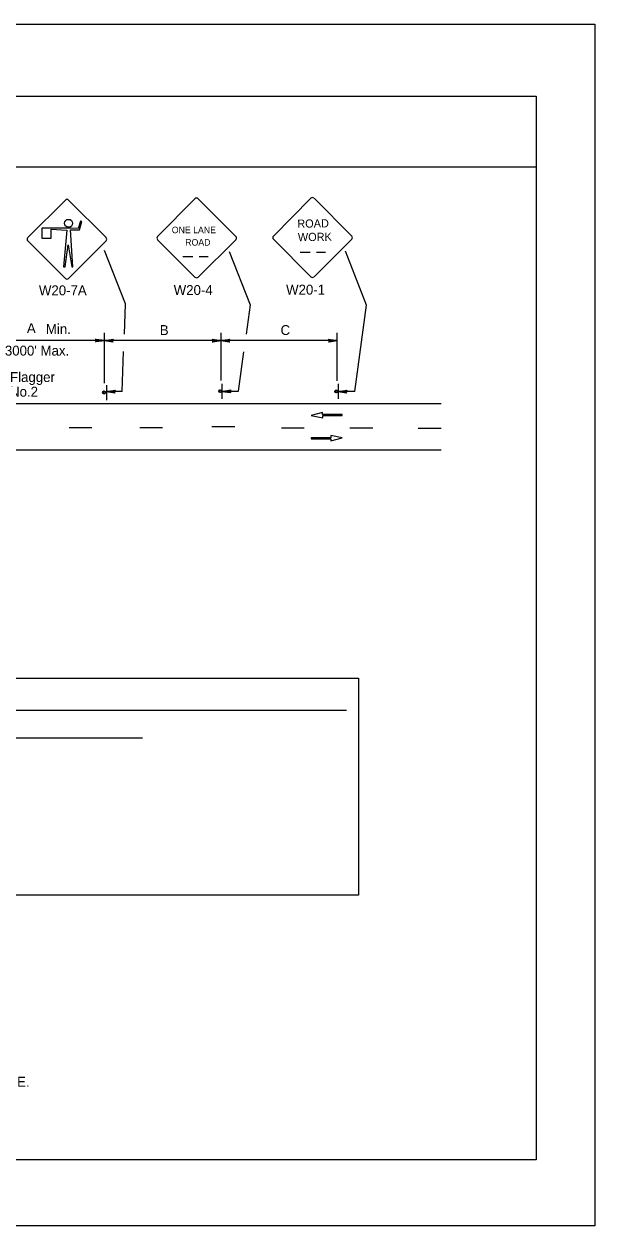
# Model space of a CAD drawing. Extents: x -14145 to -13521, y 30244 to 30661.
# Drawn here: x -13735.29 to -13723.17, y 30451.81 to 30477.31 of the extents above; entities that cross this region are included whole.
import ezdxf

# ---------------------------------------------------------------- set-up
doc = ezdxf.new("R2010")
doc.units = 0
for name, color, linetype in [('1', 7, 'Continuous'), ('10', 7, 'Continuous'), ('2', 7, 'Continuous'), ('61', 7, 'Continuous')]:
    doc.layers.add(name, color=color, linetype=linetype)

msp = doc.modelspace()

# ---------------------------------------------------------------- linework, layer by layer
at = {"layer": '1'}
for p, q in [((-13734.412, 30473.571), (-13735.207, 30472.776)), ((-13733.55, 30472.776), (-13734.345, 30473.571)), ((-13731.663, 30473.6), (-13732.458, 30472.797)), ((-13730.794, 30472.797), (-13731.596, 30473.6)), ((-13729.203, 30473.609), (-13729.998, 30472.806)), ((-13728.334, 30472.806), (-13729.136, 30473.609)), ((-13734.09, 30473.121), (-13734.142, 30472.971)), ((-13734.112, 30472.941), (-13734.067, 30473.114)), ((-13734.067, 30473.114), (-13734.09, 30473.121)), ((-13734.292, 30472.979), (-13734.915, 30472.979)), ((-13734.915, 30472.979), (-13734.915, 30472.761)), ((-13734.915, 30472.761), (-13734.712, 30472.761)), ((-13734.712, 30472.761), (-13734.712, 30472.956)), ((-13734.712, 30472.956), (-13734.382, 30472.934)), ((-13734.382, 30472.934), (-13734.45, 30472.154)), ((-13734.255, 30472.154), (-13734.307, 30472.941)), ((-13734.307, 30472.941), (-13734.112, 30472.941)), ((-13734.142, 30472.971), (-13734.292, 30472.979)), ((-13735.207, 30472.709), (-13734.412, 30471.906)), ((-13734.42, 30472.154), (-13734.352, 30472.619)), ((-13734.352, 30472.619), (-13734.277, 30472.154)), ((-13734.345, 30471.906), (-13733.55, 30472.709)), ((-13733.139, 30471.374), (-13733.582, 30472.505)), ((-13732.458, 30472.731), (-13731.663, 30471.936)), ((-13731.596, 30471.936), (-13730.794, 30472.731)), ((-13729.998, 30472.74), (-13729.203, 30471.945)), ((-13729.136, 30471.945), (-13728.334, 30472.74)), ((-13731.92, 30472.372), (-13731.71, 30472.372)), ((-13731.577, 30472.372), (-13731.384, 30472.372)), ((-13730.487, 30471.345), (-13730.93, 30472.476)), ((-13729.429, 30472.466), (-13729.219, 30472.466)), ((-13729.086, 30472.466), (-13728.893, 30472.466)), ((-13728.021, 30471.34), (-13728.47, 30472.485)), ((-13734.45, 30472.154), (-13734.42, 30472.154)), ((-13734.277, 30472.154), (-13734.255, 30472.154)), ((-13733.158, 30470.728), (-13733.138, 30471.374)), ((-13730.572, 30470.73), (-13730.487, 30471.346)), ((-13728.273, 30469.509), (-13728.021, 30471.34)), ((-13733.582, 30469.688), (-13733.582, 30470.756)), ((-13731.11, 30469.742), (-13731.11, 30470.756)), ((-13728.644, 30469.736), (-13728.644, 30470.756)), ((-13733.582, 30470.591), (-13735.994, 30470.591)), ((-13731.11, 30470.591), (-13733.582, 30470.591)), ((-13728.644, 30470.591), (-13731.11, 30470.591)), ((-13733.211, 30469.509), (-13733.178, 30470.362)), ((-13730.739, 30469.515), (-13730.624, 30470.349)), ((-13733.54, 30469.646), (-13733.54, 30469.328)), ((-13733.21, 30469.508), (-13733.54, 30469.508)), ((-13731.092, 30469.676), (-13731.092, 30469.358)), ((-13730.738, 30469.514), (-13731.092, 30469.514)), ((-13728.626, 30469.67), (-13728.626, 30469.352)), ((-13728.272, 30469.508), (-13728.626, 30469.508)), ((-13752.026, 30469.258), (-13726.438, 30469.258)), ((-13728.953, 30469.066), (-13729.194, 30469)), ((-13729.194, 30469), (-13728.95, 30468.954)), ((-13728.953, 30469.021), (-13728.953, 30469.066)), ((-13728.536, 30469.021), (-13728.953, 30469.021)), ((-13728.95, 30468.954), (-13728.95, 30468.999)), ((-13728.95, 30468.999), (-13728.536, 30468.999)), ((-13728.536, 30468.999), (-13728.536, 30469.021)), ((-13733.852, 30468.742), (-13734.332, 30468.742)), ((-13732.352, 30468.742), (-13732.832, 30468.742)), ((-13730.818, 30468.76), (-13731.304, 30468.76)), ((-13729.342, 30468.736), (-13729.828, 30468.736)), ((-13727.89, 30468.73), (-13728.376, 30468.73)), ((-13726.438, 30468.724), (-13726.924, 30468.724)), ((-13728.78, 30468.531), (-13729.194, 30468.531)), ((-13729.194, 30468.531), (-13729.194, 30468.509)), ((-13729.194, 30468.509), (-13728.777, 30468.509)), ((-13728.536, 30468.53), (-13728.78, 30468.576)), ((-13728.78, 30468.576), (-13728.78, 30468.531)), ((-13728.777, 30468.464), (-13728.536, 30468.53)), ((-13728.777, 30468.509), (-13728.777, 30468.464)), ((-13752.026, 30468.274), (-13726.438, 30468.274))]:
    msp.add_line(p, q, dxfattribs=at)
for points in [[(-13733.762, 30470.615), (-13733.756, 30470.603), (-13733.582, 30470.591), (-13733.762, 30470.615), (-13733.774, 30470.621), (-13733.582, 30470.591), (-13733.756, 30470.585), (-13733.762, 30470.573), (-13733.582, 30470.591), (-13733.774, 30470.561), (-13733.762, 30470.573)], [(-13733.408, 30470.567), (-13733.414, 30470.579), (-13733.582, 30470.591), (-13733.408, 30470.567), (-13733.396, 30470.561), (-13733.582, 30470.591), (-13733.414, 30470.597), (-13733.408, 30470.609), (-13733.582, 30470.591), (-13733.396, 30470.621), (-13733.408, 30470.609)], [(-13731.284, 30470.609), (-13731.278, 30470.597), (-13731.11, 30470.591), (-13731.284, 30470.609), (-13731.296, 30470.621), (-13731.11, 30470.591), (-13731.278, 30470.579), (-13731.284, 30470.567), (-13731.11, 30470.591), (-13731.296, 30470.561), (-13731.284, 30470.567)], [(-13730.936, 30470.567), (-13730.942, 30470.579), (-13731.11, 30470.591), (-13730.936, 30470.567), (-13730.924, 30470.561), (-13731.11, 30470.591), (-13730.942, 30470.597), (-13730.936, 30470.609), (-13731.11, 30470.591), (-13730.924, 30470.621), (-13730.936, 30470.609)], [(-13728.818, 30470.609), (-13728.812, 30470.597), (-13728.644, 30470.591), (-13728.818, 30470.609), (-13728.83, 30470.621), (-13728.644, 30470.591), (-13728.812, 30470.579), (-13728.818, 30470.567), (-13728.644, 30470.591), (-13728.83, 30470.561), (-13728.818, 30470.567)], [(-13733.366, 30469.484), (-13733.372, 30469.496), (-13733.54, 30469.508), (-13733.366, 30469.484), (-13733.354, 30469.478), (-13733.54, 30469.508), (-13733.372, 30469.514), (-13733.366, 30469.526), (-13733.54, 30469.508), (-13733.354, 30469.538), (-13733.366, 30469.526)], [(-13730.912, 30469.49), (-13730.918, 30469.502), (-13731.092, 30469.514), (-13730.912, 30469.49), (-13730.906, 30469.484), (-13731.092, 30469.514), (-13730.918, 30469.52), (-13730.912, 30469.532), (-13731.092, 30469.514), (-13730.906, 30469.544), (-13730.912, 30469.532)], [(-13728.446, 30469.484), (-13728.452, 30469.496), (-13728.626, 30469.508), (-13728.446, 30469.484), (-13728.44, 30469.478), (-13728.626, 30469.508), (-13728.452, 30469.514), (-13728.446, 30469.526), (-13728.626, 30469.508), (-13728.44, 30469.538), (-13728.446, 30469.526)]]:
    msp.add_lwpolyline(points, dxfattribs=at)
for centre, radius in [((-13734.346, 30473.079), 0.0844), ((-13733.591, 30469.488), 0.0325), ((-13731.129, 30469.519), 0.0298), ((-13728.663, 30469.513), 0.0298)]:
    msp.add_circle(centre, radius, dxfattribs=at)
for centre, radius, start, end in [((-13734.381, 30473.539), 0.0465, 45, 135), ((-13731.63, 30473.568), 0.0465, 45, 135), ((-13729.17, 30473.577), 0.0465, 45, 135), ((-13735.18, 30472.74), 0.0465, 135, 225), ((-13733.582, 30472.74), 0.0465, 315, 45), ((-13732.425, 30472.765), 0.0465, 135, 225), ((-13730.827, 30472.765), 0.0465, 315, 45), ((-13729.965, 30472.774), 0.0465, 135, 225), ((-13728.367, 30472.774), 0.0465, 315, 45), ((-13734.381, 30471.941), 0.0465, 225, 315), ((-13731.63, 30471.97), 0.0465, 225, 315), ((-13729.17, 30471.979), 0.0465, 225, 315), ((-13733.591, 30469.5), 0.0214, 355.7499, 350.479), ((-13731.128, 30469.519), 0.0214, 355.7499, 350.479), ((-13728.662, 30469.513), 0.0214, 355.7499, 350.479)]:
    msp.add_arc(centre, radius, start, end, dxfattribs=at)
at = {"layer": '10'}
for p, q in [((-13755.874, 30475.777), (-13724.422, 30475.777)), ((-13724.422, 30475.777), (-13724.422, 30453.207)), ((-13755.874, 30474.277), (-13724.422, 30474.277)), ((-13724.422, 30453.207), (-13755.874, 30453.207))]:
    msp.add_line(p, q, dxfattribs=at)
at = {"layer": '2'}
for p, q in [((-13748.3, 30462.748), (-13728.449, 30462.748)), ((-13744.212, 30462.163), (-13732.776, 30462.163))]:
    msp.add_line(p, q, dxfattribs=at)
msp.add_lwpolyline([(-13748.568, 30463.426), (-13728.191, 30463.426), (-13728.191, 30458.822), (-13748.568, 30458.822)], close=True, dxfattribs=at)
at = {"layer": '61'}
msp.add_lwpolyline([(-13756.174, 30477.307), (-13723.174, 30477.307), (-13723.174, 30451.807), (-13756.174, 30451.807)], close=True, dxfattribs=at)

# ---------------------------------------------------------------- texts
at = {"layer": '1'}
for s, height, rotation, p in [('ROAD', 0.1735, 0.7566, (-13729.49, 30472.984)), ('WORK', 0.1733, 0.7588, (-13729.478, 30472.699))]:
    msp.add_text(s, height=height, rotation=rotation, dxfattribs=at).set_placement(p)
for s, height, p in [('ONE LANE', 0.1386, (-13732.155, 30472.869)), ('ROAD', 0.1389, (-13731.87, 30472.606))]:
    msp.add_text(s, height=height, dxfattribs=at).set_placement(p)
at = {"layer": '2'}
for s, p in [('W20-7A', (-13734.975, 30471.552)), ('W20-4', (-13732.114, 30471.559)), ('W20-1', (-13729.729, 30471.567)), ('A', (-13735.23, 30470.749)), ('Min.', (-13734.827, 30470.733)), ('B', (-13732.409, 30470.709)), ('C', (-13729.846, 30470.709)), ("3000' Max.", (-13735.697, 30470.273)), ('Flagger', (-13735.587, 30469.712)), ('No.2', (-13735.587, 30469.402)), ('    b. The W20-7A Sign may be eliminated if the flagger is clearly visible to traffic for a minimum distance of E.', (-13748.734, 30454.761))]:
    msp.add_text(s, height=0.21, dxfattribs=at).set_placement(p)

doc.saveas('drawing.dxf')
